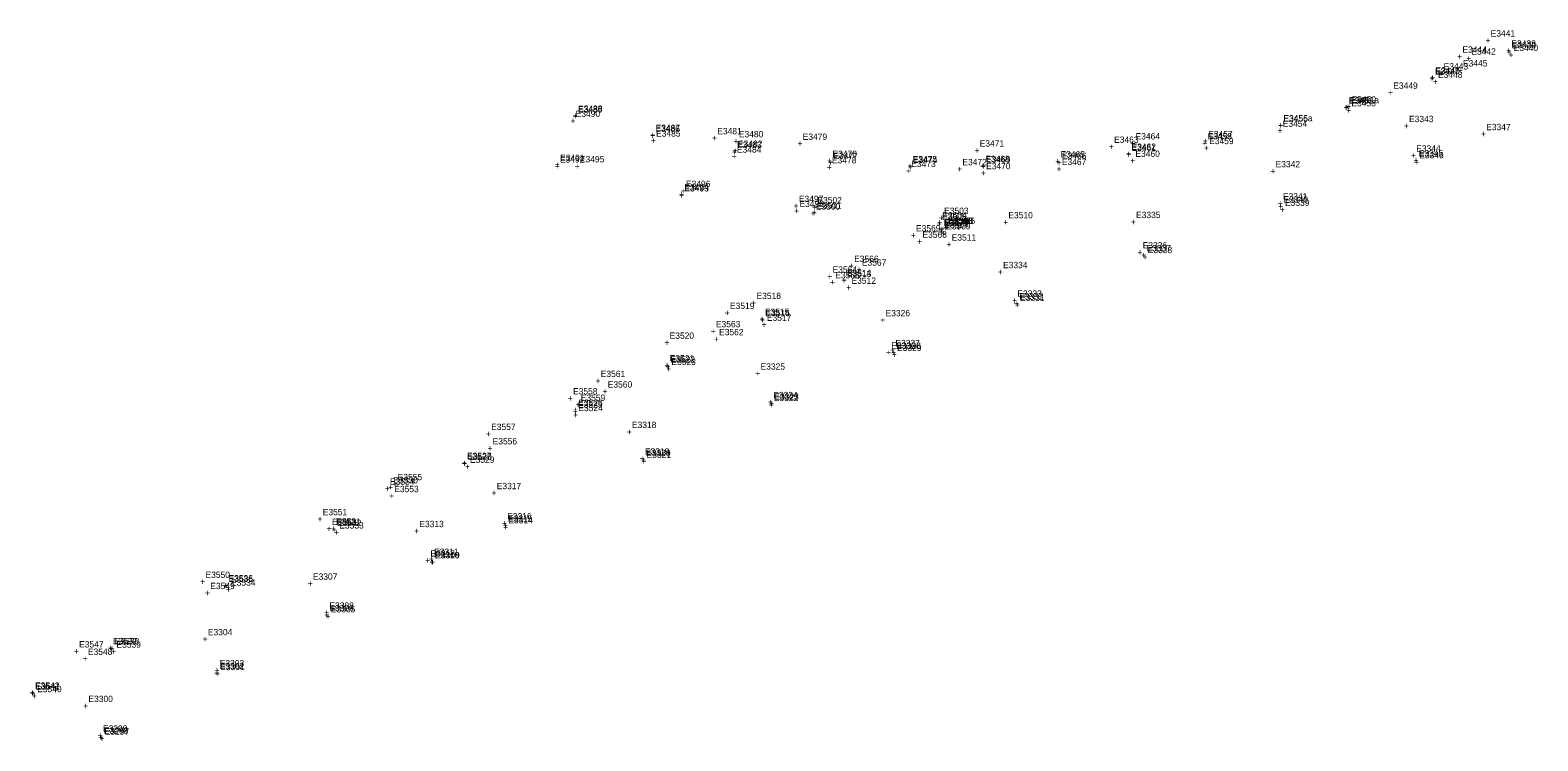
# Model space of a CAD drawing. Extents: x 1667192 to 1669644, y 336680 to 339991.
# Drawn here: x 1668501 to 1669097, y 339542 to 339823 of the extents above; entities that cross this region are included whole.
import ezdxf

# ---------------------------------------------------------------- set-up
doc = ezdxf.new("R2010")
doc.units = 0
for name, color, linetype in [('S_Control_Temp_Traverse', 7, 'Continuous'), ('S_Curb_Type_1', 7, 'Continuous'), ('S_Curb_Type_5', 7, 'Continuous'), ('S_Drainage_CB', 7, 'Continuous'), ('S_Ground_Elevation', 7, 'Continuous'), ('S_Guardrail_Beam', 7, 'Continuous'), ('S_Roadway_Edge_Pavement', 7, 'Continuous'), ('S_Roadway_Edge_TW', 7, 'Continuous'), ('S_Traffic_Post_Conc', 7, 'Continuous'), ('S_Traffic_Sign_SinglePost', 7, 'Continuous'), ('S_Utilities_GuyWire3', 7, 'Continuous'), ('S_Utilities_Pole_StreetLight', 7, 'Continuous')]:
    doc.layers.add(name, color=color, linetype=linetype)

msp = doc.modelspace()

# ---------------------------------------------------------------- texts
at = {"layer": 'S_Control_Temp_Traverse'}
for s, p in [('605', (1668868.75, 339746.08)), ('605', (1668868.75, 339746.08)), ('605', (1668868.75, 339746.08)), ('+', (1668866.69, 339743.33)), ('+', (1668866.69, 339743.33)), ('+', (1668866.69, 339743.33))]:
    msp.add_text(s, height=2.5, dxfattribs=at).set_placement(p)
at = {"layer": 'S_Curb_Type_1'}
for s, p in [('E3438', (1669086.38, 339816.16)), ('+', (1669084.32, 339813.41)), ('E3446', (1669056.36, 339805.55)), ('+', (1669054.3, 339802.8)), ('E3451a', (1669022.49, 339793.8)), ('+', (1668715.23, 339787.65)), ('E3488', (1668717.29, 339790.4)), ('E3456a', (1668996.2, 339786.66)), ('+', (1669020.43, 339791.05)), ('+', (1668745.89, 339780.05)), ('E3487', (1668747.95, 339782.8)), ('E3457', (1668966.47, 339780.34)), ('+', (1668994.14, 339783.91)), ('E3482', (1668780.52, 339776.53)), ('E3462', (1668936.14, 339775.35)), ('+', (1668964.41, 339777.59)), ('E3492', (1668710.11, 339770.32)), ('+', (1668778.46, 339773.78)), ('+', (1668815.84, 339769.79)), ('E3476', (1668817.9, 339772.54)), ('E3475', (1668849.6, 339770.45)), ('E3468', (1668878.32, 339770.53)), ('+', (1668906.01, 339769.59)), ('E3465', (1668908.07, 339772.34)), ('+', (1668934.08, 339772.6)), ('+', (1668708.05, 339767.57)), ('+', (1668847.54, 339767.7)), ('+', (1668876.26, 339767.78)), ('+', (1668757.31, 339756.14)), ('E3493', (1668759.37, 339758.89)), ('E3500', (1668811.33, 339751.71)), ('+', (1668809.27, 339748.96)), ('+', (1668859.15, 339744.86)), ('E3505', (1668861.21, 339747.61)), ('E3507', (1668862.15, 339744.39)), ('E3506', (1668863.55, 339746)), ('+', (1668860.09, 339741.64)), ('+', (1668861.49, 339743.25)), ('+', (1668821.53, 339722.67)), ('E3514', (1668823.59, 339725.42)), ('E3515', (1668791.15, 339710.02)), ('+', (1668789.08, 339707.27)), ('E3521', (1668753.54, 339691.62)), ('+', (1668751.47, 339688.87)), ('E3526', (1668717.33, 339674.03)), ('+', (1668715.27, 339671.28)), ('+', (1668671.28, 339650.29)), ('E3527', (1668673.34, 339653.04)), ('E3531', (1668621.61, 339627.08)), ('+', (1668619.55, 339624.33)), ('+', (1668576.99, 339601.85)), ('E3536', (1668579.05, 339604.6)), ('E3537', (1668533.38, 339579.77)), ('+', (1668531.32, 339577.02)), ('+', (1668500.46, 339559.37)), ('E3542', (1668502.52, 339562.12))]:
    msp.add_text(s, height=2.5, dxfattribs=at).set_placement(p)
at = {"layer": 'S_Curb_Type_5'}
for s, p in [('+', (1669047.88, 339769.23)), ('E3346', (1669049.94, 339771.98)), ('+', (1668994.81, 339750.43)), ('E3339', (1668996.87, 339753.18)), ('E3338', (1668942.58, 339734.48)), ('+', (1668940.52, 339731.73)), ('E3331', (1668892.1, 339715.55)), ('+', (1668890.04, 339712.8)), ('+', (1668841.38, 339693.05)), ('E3329', (1668843.44, 339695.8)), ('+', (1668792.67, 339673.19)), ('E3322', (1668794.73, 339675.94)), ('+', (1668742.33, 339650.72)), ('E3321', (1668744.39, 339653.47)), ('+', (1668687.65, 339624.85)), ('E3314', (1668689.71, 339627.6)), ('E3309', (1668660.83, 339613.71)), ('+', (1668658.77, 339610.96)), ('+', (1668617.45, 339589.59)), ('E3305', (1668619.51, 339592.34)), ('+', (1668573.72, 339566.75)), ('E3301', (1668575.78, 339569.5)), ('E3297', (1668530.08, 339543.95)), ('+', (1668528.02, 339541.2))]:
    msp.add_text(s, height=2.5, dxfattribs=at).set_placement(p)
at = {"layer": 'S_Drainage_CB'}
for s, p in [('+', (1669065.16, 339805.6)), ('E3445', (1669067.22, 339808.35)), ('+', (1669074.35, 339780.39)), ('E3347', (1669076.41, 339783.14)), ('E3472', (1668869.27, 339769.27)), ('+', (1668867.21, 339766.52)), ('E3330', (1668841.15, 339696.69)), ('+', (1668839.08, 339693.94)), ('E3530', (1668644.31, 339643.41)), ('+', (1668642.25, 339640.66)), ('E3312', (1668658.92, 339614.45)), ('+', (1668656.86, 339611.7))]:
    msp.add_text(s, height=2.5, dxfattribs=at).set_placement(p)
at = {"layer": 'S_Ground_Elevation'}
for s, p in [('E3570', (1668862.29, 339745.55)), ('+', (1668848.87, 339740.31)), ('E3569', (1668850.93, 339743.06)), ('E3568', (1668853.49, 339740.55)), ('+', (1668860.23, 339742.8)), ('+', (1668851.43, 339737.8)), ('E3564', (1668817.93, 339726.75)), ('+', (1668824.42, 339728.23)), ('E3566', (1668826.48, 339730.98)), ('+', (1668827.46, 339726.79)), ('E3567', (1668829.52, 339729.54)), ('+', (1668815.87, 339724)), ('+', (1668816.95, 339721.78)), ('E3565', (1668819.01, 339724.53)), ('+', (1668769.74, 339702.4)), ('E3563', (1668771.8, 339705.15)), ('E3562', (1668773.08, 339701.99)), ('+', (1668771.02, 339699.24)), ('E3561', (1668726.28, 339685.46)), ('E3558', (1668715.31, 339678.57)), ('+', (1668724.22, 339682.71)), ('+', (1668726.98, 339678.54)), ('E3560', (1668729.05, 339681.29)), ('+', (1668713.25, 339675.82)), ('+', (1668716.31, 339673.28)), ('E3559', (1668718.37, 339676.03)), ('+', (1668680.86, 339661.74)), ('E3557', (1668682.92, 339664.49)), ('+', (1668681.45, 339656.05)), ('E3556', (1668683.51, 339658.8)), ('E3554', (1668642.93, 339642.85)), ('E3555', (1668645.95, 339644.65)), ('+', (1668640.87, 339640.1)), ('+', (1668642.54, 339637.17)), ('+', (1668643.89, 339641.9)), ('E3553', (1668644.6, 339639.92)), ('E3551', (1668616.34, 339630.79)), ('+', (1668614.28, 339628.04)), ('E3552', (1668619.93, 339626.95)), ('+', (1668617.87, 339624.2)), ('+', (1668567.9, 339603.23)), ('E3550', (1668569.96, 339605.98)), ('E3549', (1668571.85, 339601.55)), ('+', (1668569.79, 339598.8)), ('E3547', (1668519.99, 339578.47)), ('+', (1668517.93, 339575.72)), ('+', (1668521.39, 339572.78)), ('E3548', (1668523.45, 339575.53))]:
    msp.add_text(s, height=2.5, dxfattribs=at).set_placement(p)
at = {"layer": 'S_Guardrail_Beam'}
for s, p in [('+', (1669076.13, 339817.43)), ('E3441', (1669078.19, 339820.18)), ('+', (1669068.48, 339810.29)), ('E3442', (1669070.54, 339813.04)), ('+', (1669057.53, 339804.39)), ('E3443', (1669059.6, 339807.14)), ('E3449', (1669039.67, 339799.51)), ('E3450', (1669023.2, 339794.07)), ('+', (1669037.61, 339796.76)), ('+', (1669021.14, 339791.32))]:
    msp.add_text(s, height=2.5, dxfattribs=at).set_placement(p)
at = {"layer": 'S_Roadway_Edge_Pavement'}
for s, p in [('E3439', (1669086.52, 339815.55)), ('+', (1669084.46, 339812.8)), ('E3447', (1669056.1, 339805.12)), ('+', (1669054.04, 339802.37)), ('E3452', (1669022.08, 339793.57)), ('+', (1668715.17, 339787.32)), ('E3489', (1668717.23, 339790.07)), ('E3455', (1668996.26, 339786.51)), ('+', (1669020.01, 339790.82)), ('E3486', (1668747.92, 339782.46)), ('E3458', (1668966.23, 339779.51)), ('+', (1668994.2, 339783.76)), ('+', (1668745.85, 339779.71)), ('E3483', (1668780.2, 339776.09)), ('E3461', (1668936.17, 339774.96)), ('+', (1668964.17, 339776.76)), ('+', (1668708.11, 339768.23)), ('E3491', (1668710.17, 339770.98)), ('+', (1668778.14, 339773.34)), ('+', (1668816.16, 339769.03)), ('E3477', (1668818.22, 339771.78)), ('E3474', (1668849.74, 339770.13)), ('E3469', (1668878.67, 339770.28)), ('+', (1668906.56, 339769.03)), ('E3466', (1668908.63, 339771.78)), ('+', (1668934.11, 339772.21)), ('+', (1669047.7, 339769.97)), ('E3345', (1669049.76, 339772.72)), ('+', (1668847.68, 339767.38)), ('+', (1668876.61, 339767.53)), ('+', (1668757.24, 339756.56)), ('E3494', (1668759.3, 339759.31)), ('E3498', (1668804.86, 339752.75)), ('E3501', (1668811.78, 339752.1)), ('+', (1668994.21, 339751.75)), ('E3340', (1668996.27, 339754.5)), ('+', (1668802.8, 339750)), ('+', (1668809.72, 339749.35)), ('+', (1668859.28, 339745.47)), ('E3504', (1668861.34, 339748.22)), ('E3509', (1668862.83, 339743.88)), ('E3508', (1668863.87, 339746.06)), ('+', (1668860.77, 339741.13)), ('+', (1668861.81, 339743.31)), ('+', (1668940.03, 339732.48)), ('E3337', (1668942.09, 339735.23)), ('+', (1668821.54, 339722.32)), ('E3513', (1668823.6, 339725.07)), ('E3332', (1668891.76, 339716.07)), ('E3516', (1668791.39, 339709.53)), ('+', (1668889.7, 339713.33)), ('+', (1668789.33, 339706.78)), ('E3328', (1668843.16, 339696.6)), ('E3522', (1668753.89, 339691.12)), ('+', (1668841.1, 339693.85)), ('+', (1668751.83, 339688.37)), ('E3525', (1668717.27, 339673.33)), ('+', (1668792.84, 339673.75)), ('E3323', (1668794.9, 339676.5)), ('+', (1668715.21, 339670.58)), ('+', (1668671.43, 339649.96)), ('E3528', (1668673.49, 339652.71)), ('+', (1668742.14, 339651.43)), ('E3320', (1668744.21, 339654.18)), ('E3532', (1668621.93, 339626.54)), ('+', (1668687.54, 339625.53)), ('E3315', (1668689.6, 339628.28)), ('+', (1668619.87, 339623.79)), ('E3310', (1668660.63, 339613.77)), ('+', (1668658.57, 339611.02)), ('+', (1668577.04, 339601.62)), ('E3535', (1668579.1, 339604.37)), ('+', (1668616.93, 339590.08)), ('E3306', (1668618.99, 339592.83)), ('E3538', (1668534.06, 339579.71)), ('+', (1668532, 339576.96)), ('+', (1668573.47, 339567.14)), ('E3302', (1668575.53, 339569.89)), ('E3541', (1668502.78, 339561.8)), ('+', (1668500.72, 339559.05)), ('+', (1668527.68, 339541.56)), ('E3298', (1668529.74, 339544.31))]:
    msp.add_text(s, height=2.5, dxfattribs=at).set_placement(p)
at = {"layer": 'S_Roadway_Edge_TW'}
for s, p in [('+', (1669085.25, 339811.73)), ('E3440', (1669087.31, 339814.48)), ('E3448', (1669057.37, 339803.81)), ('+', (1669055.31, 339801.06)), ('E3453', (1669023.11, 339792.56)), ('E3490', (1668716.34, 339788.37)), ('+', (1669021.05, 339789.81)), ('E3343', (1669045.91, 339786.32)), ('+', (1668714.28, 339785.62)), ('E3485', (1668748.15, 339780.6)), ('+', (1668993.89, 339781.71)), ('E3454', (1668995.96, 339784.46)), ('+', (1669043.85, 339783.57)), ('+', (1668746.09, 339777.85)), ('E3484', (1668780.12, 339774.26)), ('+', (1668964.8, 339774.86)), ('E3459', (1668966.86, 339777.61)), ('E3344', (1669048.73, 339774.67)), ('E3495', (1668718.02, 339770.4)), ('+', (1668778.06, 339771.51)), ('E3478', (1668817.69, 339770.03)), ('E3473', (1668849.06, 339768.55)), ('E3470', (1668878.64, 339767.7)), ('E3467', (1668908.61, 339769.32)), ('+', (1668935.64, 339769.83)), ('E3460', (1668937.71, 339772.58)), ('E3342', (1668993.14, 339768.43)), ('+', (1669046.67, 339771.92)), ('+', (1668715.96, 339767.65)), ('+', (1668815.63, 339767.28)), ('+', (1668847, 339765.8)), ('+', (1668876.58, 339764.95)), ('+', (1668906.55, 339766.57)), ('+', (1668991.08, 339765.68)), ('+', (1668757.88, 339757.88)), ('E3496', (1668759.95, 339760.63)), ('E3341', (1668996.03, 339755.71)), ('+', (1668802.54, 339751.96)), ('E3497', (1668804.61, 339754.71)), ('+', (1668809.89, 339751.45)), ('E3502', (1668811.95, 339754.2)), ('E3503', (1668862.06, 339749.99)), ('+', (1668993.96, 339752.96)), ('+', (1668860, 339747.24)), ('+', (1668885.39, 339745.51)), ('E3510', (1668887.46, 339748.26)), ('+', (1668935.88, 339745.6)), ('E3335', (1668937.95, 339748.35)), ('E3511', (1668865.05, 339739.44)), ('+', (1668862.99, 339736.69)), ('+', (1668938.53, 339733.59)), ('E3336', (1668940.59, 339736.34)), ('E3334', (1668885.36, 339728.54)), ('E3512', (1668825.42, 339722.34)), ('+', (1668883.3, 339725.79)), ('+', (1668823.36, 339719.59)), ('+', (1668888.96, 339714.49)), ('E3333', (1668891.02, 339717.24)), ('E3326', (1668838.91, 339709.52)), ('+', (1668789.9, 339704.94)), ('E3517', (1668791.96, 339707.69)), ('+', (1668836.85, 339706.77)), ('E3327', (1668842.78, 339697.67)), ('E3523', (1668754.22, 339690.21)), ('+', (1668840.72, 339694.92)), ('+', (1668752.16, 339687.46)), ('+', (1668787.4, 339685.64)), ('E3325', (1668789.46, 339688.39)), ('+', (1668792.43, 339674.34)), ('E3324', (1668794.49, 339677.09)), ('+', (1668715.34, 339669.22)), ('E3524', (1668717.4, 339671.97)), ('+', (1668736.54, 339662.53)), ('E3318', (1668738.6, 339665.28)), ('E3319', (1668743.73, 339654.79)), ('+', (1668672.49, 339648.76)), ('E3529', (1668674.55, 339651.51)), ('+', (1668741.67, 339652.04)), ('+', (1668683.09, 339638.35)), ('E3317', (1668685.15, 339641.1)), ('E3533', (1668622.87, 339625.53)), ('E3313', (1668654.53, 339626.07)), ('+', (1668687.2, 339626.38)), ('E3316', (1668689.26, 339629.13)), ('+', (1668620.81, 339622.78)), ('+', (1668652.47, 339623.32)), ('E3311', (1668660.37, 339615.07)), ('+', (1668658.31, 339612.32)), ('E3534', (1668580.04, 339602.9)), ('+', (1668610.39, 339602.5)), ('E3307', (1668612.45, 339605.25)), ('+', (1668577.98, 339600.15)), ('+', (1668616.9, 339591.06)), ('E3308', (1668618.96, 339593.81)), ('E3304', (1668570.9, 339583.3)), ('E3539', (1668534.75, 339578.35)), ('+', (1668568.84, 339580.55)), ('+', (1668532.69, 339575.6)), ('E3303', (1668575.6, 339570.99)), ('+', (1668573.54, 339568.24)), ('E3540', (1668503.4, 339560.77)), ('+', (1668501.34, 339558.02)), ('+', (1668521.61, 339554.13)), ('E3300', (1668523.67, 339556.88)), ('+', (1668527.35, 339542.4)), ('E3299', (1668529.41, 339545.15))]:
    msp.add_text(s, height=2.5, dxfattribs=at).set_placement(p)
at = {"layer": 'S_Traffic_Post_Conc'}
for s, p in [('E3571', (1668861.92, 339745.25)), ('+', (1668859.86, 339742.5))]:
    msp.add_text(s, height=2.5, dxfattribs=at).set_placement(p)
at = {"layer": 'S_Traffic_Sign_SinglePost'}
for s, p in [('+', (1669064.97, 339811.01)), ('E3444', (1669067.03, 339813.76)), ('+', (1668804.06, 339776.56)), ('E3479', (1668806.12, 339779.31)), ('+', (1668874.06, 339773.91)), ('E3471', (1668876.12, 339776.66)), ('+', (1668751.44, 339697.84)), ('E3520', (1668753.5, 339700.59))]:
    msp.add_text(s, height=2.5, dxfattribs=at).set_placement(p)
at = {"layer": 'S_Utilities_GuyWire3'}
for s, p in [('E3481', (1668772.35, 339781.53)), ('E3464', (1668937.75, 339779.46)), ('+', (1668770.29, 339778.78)), ('+', (1668935.69, 339776.71)), ('+', (1668775.3, 339709.64)), ('E3519', (1668777.37, 339712.39))]:
    msp.add_text(s, height=2.5, dxfattribs=at).set_placement(p)
at = {"layer": 'S_Utilities_Pole_StreetLight'}
for s, p in [('E3480', (1668780.88, 339780.31)), ('+', (1668778.82, 339777.56)), ('+', (1668927.21, 339775.37)), ('E3463', (1668929.27, 339778.12)), ('E3518', (1668787.86, 339716.33)), ('+', (1668785.8, 339713.58))]:
    msp.add_text(s, height=2.5, dxfattribs=at).set_placement(p)

doc.saveas('drawing.dxf')
